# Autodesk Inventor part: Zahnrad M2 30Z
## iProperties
Created: 2006-11
Part Number: Zahnrad M2 30Z
Cost Center: 0,419 kg
Material: Stahl (schweißbar)
Document SubType Name: Modeling
Designer: Schmidt
Authority: 53345 mm^3
Density: 7.86 g/cm^3
SaveDate: 2006-11-02
SaveTime: 22:48
TotalMass: 0,419 kg
TotalVolume: 53345 mm^3
Author: Schmidt
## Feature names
1. Basis1
2. Bohrung2 [Hole]
3. Bohrung3 [Hole]
4. Extrusion2
